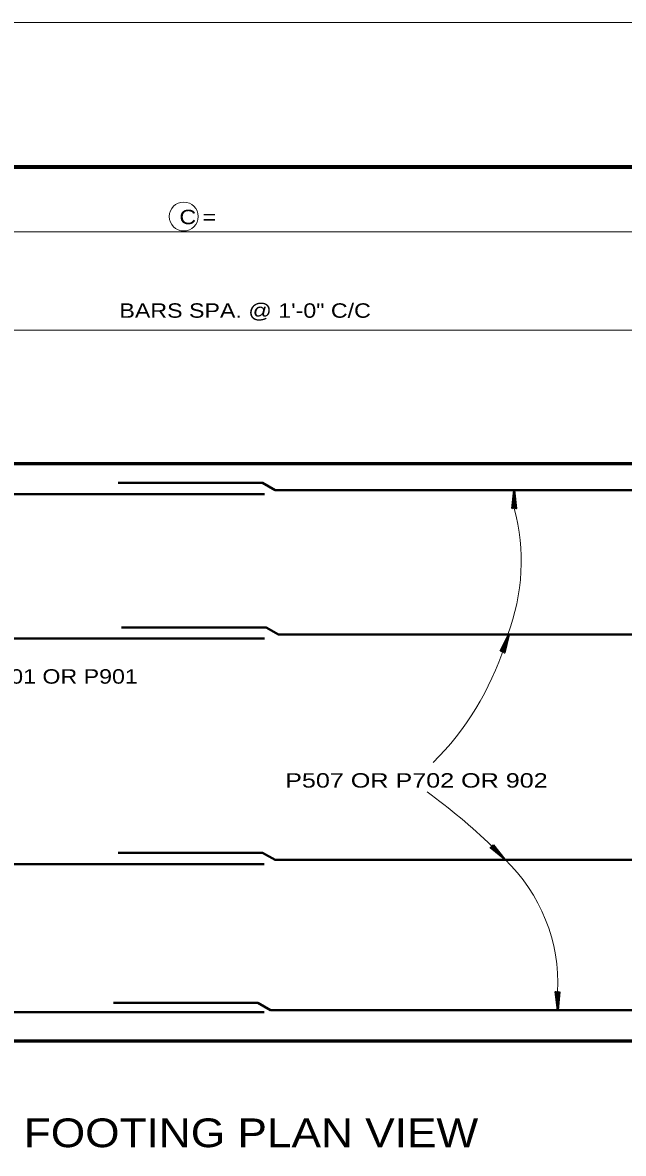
# Model space of a CAD drawing. Extents: x 4.49 to 7.69, y 0.28 to 2.27.
# Drawn here: x 5.049 to 5.396, y 1.617 to 2.269 of the extents above; entities that cross this region are included whole.
import ezdxf

# ---------------------------------------------------------------- set-up
doc = ezdxf.new("R2010")
doc.units = 0
doc.header["$LTSCALE"] = 0.0033
doc.layers.add('1', color=7, linetype='Continuous', lineweight=35)

msp = doc.modelspace()

# ---------------------------------------------------------------- linework, layer by layer
at = {"layer": '1', "lineweight": 13}
for p, q in [((4.492417, 2.2695), (7.688833, 2.2695)), ((4.79675, 2.148667), (5.547917, 2.148667)), ((4.814167, 2.092), (5.525, 2.092))]:
    msp.add_line(p, q, dxfattribs=at)
at = {"layer": '1', "lineweight": 40}
for p, q in [((4.813833, 1.997333), (5.188833, 1.997333)), ((4.813833, 1.914), (5.188833, 1.914)), ((4.813833, 1.914), (5.188833, 1.914)), ((4.813583, 1.783833), (5.188583, 1.783833)), ((4.813667, 1.698333), (5.188667, 1.698333))]:
    msp.add_line(p, q, dxfattribs=at)
at = {"layer": '1'}
for p, q in [((5.331833, 1.989417), (5.33275, 1.99725)), ((5.331833, 1.989417), (5.33275, 1.99725)), ((5.331917, 1.989417), (5.33275, 1.99725)), ((5.332, 1.989417), (5.332833, 1.99725)), ((5.332, 1.989417), (5.333, 1.99725)), ((5.332833, 1.989167), (5.332833, 1.99975)), ((5.3335, 1.989333), (5.33275, 1.996667)), ((5.333667, 1.989417), (5.332833, 1.99675)), ((5.33375, 1.989417), (5.333, 1.99675)), ((5.333917, 1.989417), (5.333083, 1.99675)), ((5.32525, 1.906833), (5.32875, 1.913917)), ((5.32525, 1.906833), (5.32875, 1.913917)), ((5.325333, 1.90675), (5.32875, 1.913917)), ((5.325417, 1.90675), (5.328833, 1.913833)), ((5.325417, 1.90675), (5.328917, 1.91375)), ((5.326083, 1.906333), (5.329667, 1.91625)), ((5.326667, 1.906167), (5.328583, 1.913333)), ((5.326917, 1.90625), (5.328667, 1.913417)), ((5.327, 1.906167), (5.328833, 1.913333)), ((5.327167, 1.906083), (5.328917, 1.913333)), ((5.320833, 1.79475), (5.325833, 1.788583)), ((5.320833, 1.794667), (5.325667, 1.7885)), ((5.320833, 1.794667), (5.325667, 1.788417)), ((5.320917, 1.79475), (5.325833, 1.788583)), ((5.320917, 1.79475), (5.325833, 1.788583)), ((5.319417, 1.793333), (5.32525, 1.788667)), ((5.319583, 1.7935), (5.325417, 1.788917)), ((5.319583, 1.793417), (5.32525, 1.78875)), ((5.319667, 1.793667), (5.325417, 1.789)), ((5.32, 1.79425), (5.327417, 1.78675)), ((5.356833, 1.71), (5.357667, 1.702667)), ((5.357, 1.71), (5.35775, 1.702667)), ((5.357083, 1.71), (5.357917, 1.702667)), ((5.35725, 1.710083), (5.358, 1.70275)), ((5.35875, 1.71), (5.35775, 1.702167)), ((5.357917, 1.71025), (5.357917, 1.699667)), ((5.35875, 1.71), (5.357917, 1.702167)), ((5.358917, 1.71), (5.358, 1.702167)), ((5.358917, 1.71), (5.358, 1.702167)), ((5.358833, 1.71), (5.358, 1.702167))]:
    msp.add_line(p, q, dxfattribs=at)
at = {"layer": '1', "lineweight": 60}
msp.add_line((5.547, 1.681667), (4.796917, 1.681667), dxfattribs=at)
at = {"layer": '1', "lineweight": 70}
msp.add_lwpolyline([(7.605833, 0.366083), (7.605833, 2.186167), (4.659167, 2.186167), (4.659167, 0.366083)], dxfattribs=at)
at = {"layer": '1', "lineweight": 60}
msp.add_lwpolyline([(4.796917, 2.015), (5.014, 2.015), (5.54675, 2.015)], dxfattribs=at)
at = {"layer": '1', "lineweight": 40}
for points in [[(5.104417, 2.003917), (5.18775, 2.003917), (5.195, 1.99975), (5.531917, 1.99975)], [(5.106417, 1.9205), (5.18975, 1.9205), (5.197, 1.916333), (5.533917, 1.916333)], [(5.104417, 1.790417), (5.18775, 1.790417), (5.195, 1.78625), (5.531917, 1.78625)], [(5.10175, 1.70375), (5.185083, 1.70375), (5.192333, 1.699583), (5.52925, 1.699583)]]:
    msp.add_lwpolyline(points, dxfattribs=at)
at = {"layer": '1'}
for points in [[(5.33175, 1.989167), (5.332833, 1.99975), (5.334, 1.989167), (5.332833, 1.98975)], [(5.33275, 1.989917), (5.332667, 1.994583), (5.33275, 1.994583), (5.33275, 1.993667), (5.332667, 1.989917), (5.332583, 1.992917), (5.3325, 1.98975), (5.332417, 1.992), (5.332333, 1.98975), (5.332583, 1.99325), (5.33275, 1.997917), (5.333, 1.997), (5.333, 1.99825), (5.333, 1.989917), (5.333167, 1.992333), (5.333167, 1.98975), (5.33275, 1.995083), (5.333417, 1.98975)], [(5.325, 1.906667), (5.329667, 1.91625), (5.327167, 1.905833), (5.32625, 1.90675)], [(5.32625, 1.907), (5.32775, 1.911333), (5.327833, 1.911333), (5.327583, 1.910583), (5.326167, 1.907), (5.327083, 1.909833), (5.325917, 1.906917), (5.326583, 1.909083), (5.32575, 1.907), (5.32725, 1.910167), (5.328917, 1.9145), (5.328833, 1.913583), (5.329333, 1.91475), (5.3265, 1.906917), (5.327417, 1.909083), (5.326583, 1.906667), (5.328, 1.911833), (5.326833, 1.906583)], [(5.320833, 1.795), (5.327417, 1.78675), (5.319167, 1.793417), (5.320417, 1.79375)], [(5.320667, 1.79375), (5.324, 1.7905), (5.323917, 1.7905), (5.32325, 1.791083), (5.320667, 1.793833), (5.322833, 1.79175), (5.320667, 1.794083), (5.32225, 1.7925), (5.320833, 1.794167), (5.323, 1.7915), (5.32625, 1.788083), (5.3255, 1.7885), (5.32625, 1.787667), (5.320417, 1.793583), (5.322083, 1.79175), (5.32025, 1.793583), (5.32425, 1.790083), (5.320083, 1.793333)], [(5.359, 1.71025), (5.357917, 1.699667), (5.35675, 1.71025), (5.357917, 1.709667)], [(5.358, 1.7095), (5.358083, 1.704833), (5.358, 1.704833), (5.358, 1.70575), (5.358083, 1.7095), (5.358167, 1.7065), (5.35825, 1.709667), (5.358333, 1.707417), (5.358417, 1.709667), (5.358167, 1.706167), (5.358, 1.7015), (5.35775, 1.702417), (5.35775, 1.701167), (5.35775, 1.7095), (5.357583, 1.707083), (5.357583, 1.709667), (5.358, 1.704333), (5.357333, 1.709667)]]:
    msp.add_lwpolyline(points, close=True, dxfattribs=at)
for points in [[(5.33275, 1.989917), (5.332, 1.9895), (5.33225, 1.98975), (5.332583, 1.989917), (5.3325, 1.990167), (5.332167, 1.99), (5.332917, 1.989833), (5.333417, 1.989667), (5.333833, 1.989417)], [(5.32625, 1.907), (5.325417, 1.906833), (5.325667, 1.907), (5.326083, 1.907083), (5.326083, 1.907333), (5.325667, 1.90725), (5.326417, 1.906833), (5.326833, 1.9065), (5.327083, 1.906083)], [(5.320667, 1.79375), (5.320833, 1.794583), (5.320833, 1.79425), (5.32075, 1.793917), (5.321, 1.79375), (5.321083, 1.794167), (5.320417, 1.79375), (5.32, 1.7935), (5.319417, 1.793333)], [(5.358, 1.7095), (5.35875, 1.709917), (5.3585, 1.709667), (5.358167, 1.7095), (5.35825, 1.70925), (5.358583, 1.709417), (5.357833, 1.709583), (5.357333, 1.70975), (5.356917, 1.71)]]:
    msp.add_lwpolyline(points, dxfattribs=at)
at = {"layer": '1', "lineweight": 13}
msp.add_circle((5.14225, 2.157583), 0.008333, dxfattribs=at)
for centre, radius, start, end in [((5.219217, 1.958503), 0.117681, 339.00173, 15.10346), ((5.167883, 1.960893), 0.167355, 314.97339, 342.20777), ((5.067069, 1.53022), 0.365631, 46.22994, 53.88334), ((5.258507, 1.714946), 0.09952, 357.29531, 46.17832)]:
    msp.add_arc(centre, radius, start, end, dxfattribs=at)

# ---------------------------------------------------------------- texts
at = {"layer": '1'}
for s, height, width, p in [('C =      ', 0.008334, 1.2, (5.13975, 2.153167)), ('BARS SPA. @ 1\'-0" C/C', 0.008334, 1.2, (5.105167, 2.099167)), ('P506 OR P701 OR P901', 0.008334, 1.2, (4.967083, 1.888)), ('P507 OR P702 OR 902', 0.008334, 1.3, (5.20075, 1.828)), ('FOOTING PLAN VIEW', 0.01658, 1.15, (5.05, 1.6205))]:
    msp.add_text(s, height=height, dxfattribs=dict(at, width=width)).set_placement(p)

doc.saveas('drawing.dxf')
